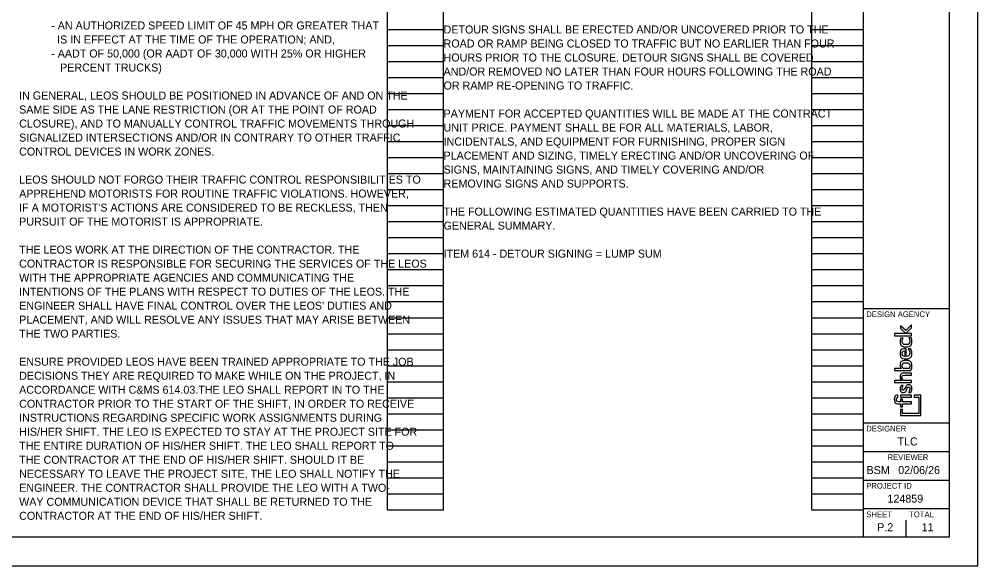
# Model space of a CAD drawing. Extents: x -11.6 to 64.7, y 0 to 22.
# Drawn here: x 17.24 to 34, y 0 to 9.56 of the extents above; entities that cross this region are included whole.
import ezdxf

# ---------------------------------------------------------------- set-up
doc = ezdxf.new("R2010")
doc.units = 0
for name, color, linetype in [('SH_Border', 7, 'Continuous'), ('SH_Cut_Line', 7, 'Continuous'), ('SH_Data', 7, 'Continuous'), ('SH_Text', 7, 'Continuous')]:
    doc.layers.add(name, color=color, linetype=linetype)

msp = doc.modelspace()

# ---------------------------------------------------------------- linework, layer by layer
at = {"layer": 'SH_Border'}
for p, q in [((32, 0.5), (32, 21.5)), ((32, 4.5), (33.5, 4.5)), ((32, 2.5), (33.5, 2.5)), ((32, 2), (33.5, 2)), ((32, 1.5), (33.5, 1.5)), ((32, 1), (33.5, 1))]:
    msp.add_line(p, q, dxfattribs=at)
msp.add_lwpolyline([(1.5, 21.5), (33.5, 21.5), (33.5, 0.5), (1.5, 0.5)], close=True, dxfattribs=at)
at = {"layer": 'SH_Cut_Line'}
msp.add_lwpolyline([(0, 0), (34, 0), (34, 22), (0, 22)], close=True, dxfattribs=at)
at = {"layer": 'SH_Data'}
for p, q in [((23.68, 0.98), (23.68, 21.14)), ((24.66, 0.98), (24.66, 21.14)), ((31.1, 0.98), (31.1, 21.14)), ((32, 0.98), (32, 21.14)), ((23.68, 9.38), (24.66, 9.38)), ((31.1, 9.38), (32, 9.38)), ((23.68, 9.1), (24.66, 9.1)), ((31.1, 9.1), (32, 9.1)), ((23.68, 8.82), (24.66, 8.82)), ((31.1, 8.82), (32, 8.82)), ((23.68, 8.54), (24.66, 8.54)), ((31.1, 8.54), (32, 8.54)), ((23.68, 8.26), (24.66, 8.26)), ((31.1, 8.26), (32, 8.26)), ((23.68, 7.98), (24.66, 7.98)), ((31.1, 7.98), (32, 7.98)), ((23.68, 7.7), (24.66, 7.7)), ((31.1, 7.7), (32, 7.7)), ((23.68, 7.42), (24.66, 7.42)), ((31.1, 7.42), (32, 7.42)), ((23.68, 7.14), (24.66, 7.14)), ((31.1, 7.14), (32, 7.14)), ((23.68, 6.86), (24.66, 6.86)), ((31.1, 6.86), (32, 6.86)), ((23.68, 6.58), (24.66, 6.58)), ((31.1, 6.58), (32, 6.58)), ((23.68, 6.3), (24.66, 6.3)), ((31.1, 6.3), (32, 6.3)), ((23.68, 6.02), (24.66, 6.02)), ((31.1, 6.02), (32, 6.02)), ((23.68, 5.74), (24.66, 5.74)), ((31.1, 5.74), (32, 5.74)), ((23.68, 5.46), (24.66, 5.46)), ((31.1, 5.46), (32, 5.46)), ((23.68, 5.18), (24.66, 5.18)), ((31.1, 5.18), (32, 5.18)), ((23.68, 4.9), (24.66, 4.9)), ((31.1, 4.9), (32, 4.9)), ((23.68, 4.62), (24.66, 4.62)), ((31.1, 4.62), (32, 4.62)), ((23.68, 4.34), (24.66, 4.34)), ((31.1, 4.34), (32, 4.34)), ((32.646, 4.198), (32.646, 4.151)), ((32.742, 4.114), (32.646, 4.198)), ((32.842, 4.215), (32.742, 4.114)), ((32.842, 4.163), (32.842, 4.215)), ((23.68, 4.06), (24.66, 4.06)), ((31.1, 4.06), (32, 4.06)), ((32.544, 4.063), (32.544, 4.024)), ((32.842, 4.063), (32.544, 4.063)), ((32.544, 4.024), (32.842, 4.024)), ((32.646, 4.151), (32.742, 4.065)), ((32.742, 4.065), (32.842, 4.163)), ((32.842, 4.024), (32.842, 4.063)), ((32.697, 3.983), (32.656, 3.983)), ((32.835, 3.987), (32.796, 3.987)), ((23.68, 3.78), (24.66, 3.78)), ((31.1, 3.78), (32, 3.78)), ((32.724, 3.758), (32.724, 3.66)), ((32.75, 3.659), (32.75, 3.797)), ((32.823, 3.793), (32.785, 3.793)), ((23.68, 3.5), (24.66, 3.5)), ((31.1, 3.5), (32, 3.5)), ((32.803, 3.454), (32.697, 3.454)), ((32.75, 3.5), (32.75, 3.5)), ((23.68, 3.22), (24.66, 3.22)), ((31.1, 3.22), (32, 3.22)), ((32.697, 3.156), (32.658, 3.156)), ((32.786, 3.032), (32.828, 3.032)), ((23.68, 2.94), (24.66, 2.94)), ((31.1, 2.94), (32, 2.94)), ((32.603, 2.948), (32.603, 2.987)), ((32.646, 2.987), (32.646, 2.948)), ((32.842, 2.987), (32.646, 2.987)), ((32.646, 2.948), (32.842, 2.948)), ((32.842, 2.948), (32.842, 2.987)), ((33.005, 2.987), (32.885, 2.987)), ((32.885, 2.987), (32.885, 2.948)), ((32.885, 2.948), (32.966, 2.948)), ((32.966, 2.948), (32.966, 2.667)), ((33.005, 2.628), (33.005, 2.987)), ((32.685, 2.734), (32.646, 2.734)), ((32.646, 2.734), (32.646, 2.628)), ((32.685, 2.667), (32.685, 2.734)), ((23.68, 2.66), (24.66, 2.66)), ((31.1, 2.66), (32, 2.66)), ((32.646, 2.628), (33.005, 2.628)), ((32.966, 2.667), (32.685, 2.667)), ((23.68, 2.38), (24.66, 2.38)), ((31.1, 2.38), (32, 2.38)), ((23.68, 2.1), (24.66, 2.1)), ((31.1, 2.1), (32, 2.1)), ((23.68, 1.82), (24.66, 1.82)), ((31.1, 1.82), (32, 1.82)), ((23.68, 1.54), (24.66, 1.54)), ((31.1, 1.54), (32, 1.54)), ((23.68, 1.26), (24.66, 1.26)), ((31.1, 1.26), (32, 1.26)), ((23.68, 0.98), (24.66, 0.98)), ((31.1, 0.98), (32, 0.98)), ((32.375, 0.675), (32.375, 0.675)), ((32.75, 0.5), (32.75, 0.8))]:
    msp.add_line(p, q, dxfattribs=at)
for points in [[(32.66, 3.454), (32.544, 3.454), (32.544, 3.415), (32.831, 3.415)], [(32.721, 3.332), (32.842, 3.332), (32.842, 3.37), (32.722, 3.37)], [(32.672, 3.245), (32.672, 3.244), (32.544, 3.244), (32.544, 3.205), (32.842, 3.205), (32.842, 3.244), (32.701, 3.244)], [(32.646, 2.831), (32.646, 2.778), (32.685, 2.778), (32.685, 2.831), (32.842, 2.831), (32.842, 2.869), (32.685, 2.869), (32.685, 2.913), (32.646, 2.913), (32.646, 2.869)]]:
    msp.add_lwpolyline(points, dxfattribs=at)
for points in [[(32.656, 3.983), (32.647, 3.964), (32.642, 3.949), (32.642, 3.926), (32.642, 3.867), (32.683, 3.829), (32.748, 3.829), (32.805, 3.829), (32.846, 3.87), (32.846, 3.929), (32.846, 3.949), (32.841, 3.974), (32.835, 3.987)], [(32.796, 3.987), (32.805, 3.968), (32.809, 3.952), (32.809, 3.935), (32.809, 3.895), (32.785, 3.869), (32.744, 3.869), (32.705, 3.869), (32.678, 3.894), (32.678, 3.929), (32.678, 3.946), (32.682, 3.961), (32.697, 3.983)], [(32.75, 3.797), (32.677, 3.797), (32.642, 3.764), (32.642, 3.712), (32.642, 3.658), (32.682, 3.62), (32.742, 3.62), (32.796, 3.62), (32.846, 3.654), (32.846, 3.715), (32.846, 3.748), (32.839, 3.77), (32.823, 3.793)], [(32.724, 3.66), (32.693, 3.665), (32.676, 3.683), (32.676, 3.713), (32.676, 3.74), (32.695, 3.757), (32.724, 3.758)], [(32.785, 3.793), (32.8, 3.771), (32.809, 3.748), (32.809, 3.725), (32.809, 3.687), (32.789, 3.665), (32.75, 3.659)], [(32.831, 3.415), (32.84, 3.435), (32.846, 3.462), (32.846, 3.488), (32.846, 3.554), (32.806, 3.593), (32.74, 3.593), (32.684, 3.593), (32.642, 3.557), (32.642, 3.508), (32.642, 3.489), (32.648, 3.471), (32.66, 3.454)], [(32.697, 3.454), (32.682, 3.471), (32.677, 3.483), (32.677, 3.499), (32.677, 3.531), (32.704, 3.553), (32.746, 3.553), (32.783, 3.553), (32.809, 3.528), (32.809, 3.493), (32.809, 3.482), (32.807, 3.466), (32.803, 3.454)], [(32.722, 3.37), (32.668, 3.37), (32.642, 3.342), (32.642, 3.304), (32.642, 3.282), (32.653, 3.26), (32.672, 3.245)], [(32.701, 3.244), (32.681, 3.263), (32.673, 3.276), (32.673, 3.293), (32.673, 3.317), (32.692, 3.332), (32.721, 3.332)], [(32.658, 3.156), (32.647, 3.135), (32.642, 3.116), (32.642, 3.098), (32.642, 3.059), (32.662, 3.033), (32.695, 3.033), (32.748, 3.033), (32.763, 3.125), (32.79, 3.125), (32.804, 3.125), (32.811, 3.112), (32.812, 3.096), (32.812, 3.08), (32.804, 3.057), (32.786, 3.032)], [(32.828, 3.032), (32.841, 3.057), (32.846, 3.076), (32.846, 3.1), (32.846, 3.137), (32.823, 3.165), (32.788, 3.165), (32.768, 3.165), (32.755, 3.153), (32.733, 3.121), (32.713, 3.086), (32.703, 3.073), (32.694, 3.073), (32.684, 3.073), (32.676, 3.083), (32.676, 3.099), (32.676, 3.113), (32.682, 3.134), (32.697, 3.156)], [(32.603, 2.987), (32.565, 2.986), (32.54, 2.957), (32.54, 2.914), (32.54, 2.86), (32.574, 2.829), (32.646, 2.831)], [(32.646, 2.869), (32.598, 2.866), (32.575, 2.882), (32.575, 2.913), (32.575, 2.931), (32.584, 2.941), (32.603, 2.948)]]:
    msp.add_open_spline(points, degree=3, dxfattribs=at)

# ---------------------------------------------------------------- texts
for s, height, p in [('DESIGN AGENCY', 0.1, (32.05, 4.35)), ('DESIGNER', 0.1, (32.05, 2.35)), ('TLC', 0.14, (32.595, 2.105)), ('REVIEWER', 0.1, (32.422, 1.85)), ('BSM', 0.14, (32.054, 1.605)), ('02/06/26', 0.14, (32.609, 1.605)), ('PROJECT ID', 0.1, (32.05, 1.35)), ('124859', 0.14, (32.42, 1.105)), ('SHEET', 0.1, (32.05, 0.85)), ('TOTAL', 0.1, (32.8, 0.85)), ('P.2', 0.14, (32.24, 0.605)), ('11', 0.14, (33.019, 0.605))]:
    msp.add_text(s, height=height, dxfattribs=at).set_placement(p)
at = {"layer": 'SH_Text'}
for s, p in [('- AN AUTHORIZED SPEED LIMIT OF 45 MPH OR GREATER THAT ', (17.8, 9.38)), ('DETOUR SIGNS SHALL BE ERECTED AND/OR UNCOVERED PRIOR TO THE', (24.66, 9.31)), ('  IS IN EFFECT AT THE TIME OF THE OPERATION; AND,', (17.8, 9.135)), ('ROAD OR RAMP BEING CLOSED TO TRAFFIC BUT NO EARLIER THAN FOUR', (24.66, 9.065)), ('- AADT OF 50,000 (OR AADT OF 30,000 WITH 25% OR HIGHER', (17.8, 8.89)), ('HOURS PRIOR TO THE CLOSURE. DETOUR SIGNS SHALL BE COVERED ', (24.66, 8.82)), ('   PERCENT TRUCKS)', (17.8, 8.645)), ('AND/OR REMOVED NO LATER THAN FOUR HOURS FOLLOWING THE ROAD', (24.66, 8.575)), ('OR RAMP RE-OPENING TO TRAFFIC.', (24.66, 8.33)), ('IN GENERAL, LEOS SHOULD BE POSITIONED IN ADVANCE OF AND ON THE', (17.24, 8.155)), ('SAME SIDE AS THE LANE RESTRICTION (OR AT THE POINT OF ROAD ', (17.24, 7.91)), ('PAYMENT FOR ACCEPTED QUANTITIES WILL BE MADE AT THE CONTRACT', (24.66, 7.84)), ('CLOSURE), AND TO MANUALLY CONTROL TRAFFIC MOVEMENTS THROUGH ', (17.24, 7.665)), ('UNIT PRICE. PAYMENT SHALL BE FOR ALL MATERIALS, LABOR, ', (24.66, 7.595)), ('SIGNALIZED INTERSECTIONS AND/OR IN CONTRARY TO OTHER TRAFFIC ', (17.24, 7.42)), ('INCIDENTALS, AND EQUIPMENT FOR FURNISHING, PROPER SIGN ', (24.66, 7.35)), ('CONTROL DEVICES IN WORK ZONES.', (17.24, 7.175)), ('PLACEMENT AND SIZING, TIMELY ERECTING AND/OR UNCOVERING OF', (24.66, 7.105)), ('SIGNS, MAINTAINING SIGNS, AND TIMELY COVERING AND/OR ', (24.66, 6.86)), ('LEOS SHOULD NOT FORGO THEIR TRAFFIC CONTROL RESPONSIBILITIES TO', (17.24, 6.685)), ('REMOVING SIGNS AND SUPPORTS.', (24.66, 6.615)), ('APPREHEND MOTORISTS FOR ROUTINE TRAFFIC VIOLATIONS. HOWEVER,', (17.24, 6.44)), ("IF A MOTORIST'S ACTIONS ARE CONSIDERED TO BE RECKLESS, THEN ", (17.24, 6.195)), ('THE FOLLOWING ESTIMATED QUANTITIES HAVE BEEN CARRIED TO THE', (24.66, 6.125)), ('PURSUIT OF THE MOTORIST IS APPROPRIATE.', (17.24, 5.95)), ('GENERAL SUMMARY.', (24.66, 5.88)), ('THE LEOS WORK AT THE DIRECTION OF THE CONTRACTOR. THE ', (17.24, 5.46)), ('ITEM 614 - DETOUR SIGNING = LUMP SUM', (24.66, 5.39)), ('CONTRACTOR IS RESPONSIBLE FOR SECURING THE SERVICES OF THE LEOS ', (17.24, 5.215)), ('WITH THE APPROPRIATE AGENCIES AND COMMUNICATING THE ', (17.24, 4.97)), ('INTENTIONS OF THE PLANS WITH RESPECT TO DUTIES OF THE LEOS. THE ', (17.24, 4.725)), ("ENGINEER SHALL HAVE FINAL CONTROL OVER THE LEOS' DUTIES AND", (17.24, 4.48)), ('PLACEMENT, AND WILL RESOLVE ANY ISSUES THAT MAY ARISE BETWEEN', (17.24, 4.235)), ('THE TWO PARTIES.', (17.24, 3.99)), ('ENSURE PROVIDED LEOS HAVE BEEN TRAINED APPROPRIATE TO THE JOB ', (17.24, 3.5)), ('DECISIONS THEY ARE REQUIRED TO MAKE WHILE ON THE PROJECT, IN ', (17.24, 3.255)), ('ACCORDANCE WITH C&MS 614.03.THE LEO SHALL REPORT IN TO THE ', (17.24, 3.01)), ('CONTRACTOR PRIOR TO THE START OF THE SHIFT, IN ORDER TO RECEIVE ', (17.24, 2.765)), ('INSTRUCTIONS REGARDING SPECIFIC WORK ASSIGNMENTS DURING ', (17.24, 2.52)), ('HIS/HER SHIFT. THE LEO IS EXPECTED TO STAY AT THE PROJECT SITE FOR', (17.24, 2.275)), ('THE ENTIRE DURATION OF HIS/HER SHIFT. THE LEO SHALL REPORT TO ', (17.24, 2.03)), ('THE CONTRACTOR AT THE END OF HIS/HER SHIFT. SHOULD IT BE ', (17.24, 1.785)), ('NECESSARY TO LEAVE THE PROJECT SITE, THE LEO SHALL NOTIFY THE ', (17.24, 1.54)), ('ENGINEER. THE CONTRACTOR SHALL PROVIDE THE LEO WITH A TWO-', (17.24, 1.295)), ('WAY COMMUNICATION DEVICE THAT SHALL BE RETURNED TO THE ', (17.24, 1.05)), ('CONTRACTOR AT THE END OF HIS/HER SHIFT.', (17.24, 0.805))]:
    msp.add_text(s, height=0.14, dxfattribs=at).set_placement(p)

doc.saveas('drawing.dxf')
